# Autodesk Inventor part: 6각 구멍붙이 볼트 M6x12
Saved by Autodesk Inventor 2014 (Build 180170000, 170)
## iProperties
Created: 2026-05
Part Number: 6각 구멍붙이 볼트 M6x12
Material: 강철, 연강
Document SubType Name: Modeling
Designer: dg
Density: 7.86 g/cm^3
Appearance: 강철
Mass: 5.70484 g
Surface Area: 6.13303 cm^2
Volume: 0.725807 cm^3
Author: jhkim
Description: 6각머리 태핑 나사
Creation Date: 2026-04-23
Sending System: Autodesk Inventor 2027
Preprocessor: ST-DEVELOPER v20.1
Author: dg
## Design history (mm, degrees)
node "6각 구멍붙이 볼트 M6x121"
body "Solid1"
node "기준1"
